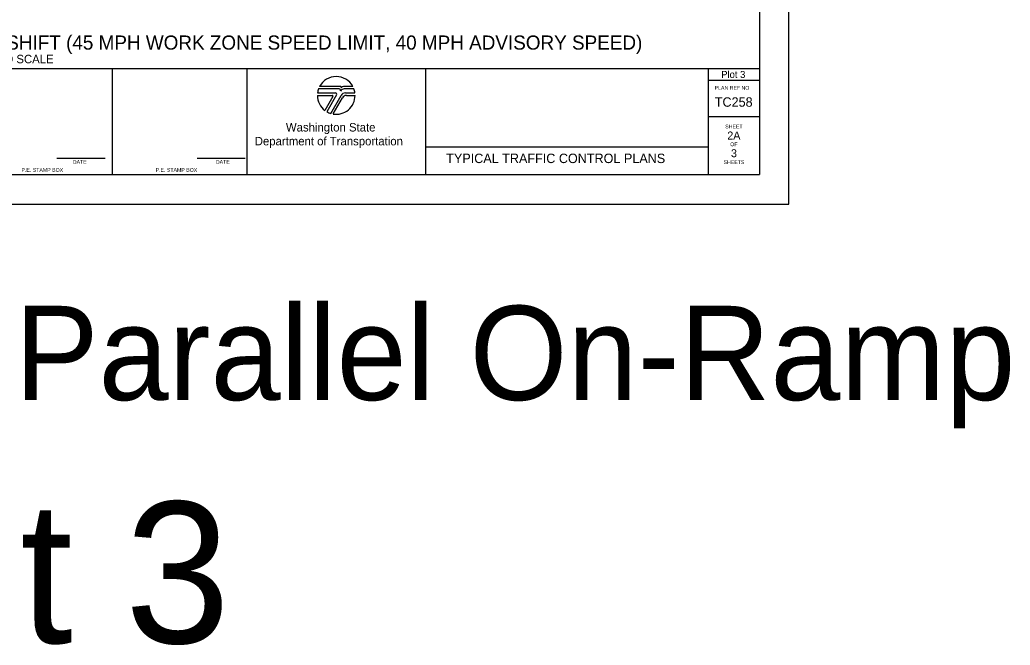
# Model space of a CAD drawing. Extents: x 99999 to 100116, y 99995 to 100013.
# Drawn here: x 100047.9 to 100058.41, y 99995.01 to 100001.64 of the extents above; entities that cross this region are included whole.
import ezdxf

# ---------------------------------------------------------------- set-up
doc = ezdxf.new("R2010")
doc.units = 0
for name, color, linetype in [('SH_DE_DetailHeading1Text', 7, 'Continuous'), ('SH_GI_PlotLimits', 7, 'Continuous'), ('SH_GI_SheetBorder', 7, 'Continuous'), ('SH_GI_SheetLocationText', 7, 'Continuous'), ('SH_GI_SheetTextInCells', 7, 'Continuous'), ('SH_GI_TitleBlockText', 7, 'Continuous'), ('SH_GI_WSDOTLogo', 7, 'Continuous')]:
    doc.layers.add(name, color=color, linetype=linetype)

msp = doc.modelspace()

# ---------------------------------------------------------------- linework, layer by layer
at = {"layer": 'SH_GI_PlotLimits'}
msp.add_lwpolyline([(100039.062, 99999.687), (100056.062, 99999.687), (100056.062, 100010.687), (100039.062, 100010.687)], close=True, dxfattribs=at)
at = {"layer": 'SH_GI_SheetBorder'}
for p, q in [((100055.75, 100010.375), (100055.75, 100000)), ((100040, 100001.126), (100055.75, 100001.126)), ((100048.883, 100000), (100048.883, 100001.126)), ((100050.309, 100001.126), (100050.309, 100000)), ((100052.205, 100001.126), (100052.205, 100000)), ((100055.208, 100001.126), (100055.208, 100000)), ((100055.208, 100001.001), (100055.75, 100001.001)), ((100055.208, 100000.618), (100055.75, 100000.618)), ((100052.205, 100000.295), (100055.208, 100000.295)), ((100048.29, 100000.173), (100048.802, 100000.173)), ((100049.78, 100000.173), (100050.291, 100000.173)), ((100040, 100000), (100055.75, 100000))]:
    msp.add_line(p, q, dxfattribs=at)
at = {"layer": 'SH_GI_WSDOTLogo'}
for p, q in [((100051.303, 100000.935), (100051.081, 100000.935)), ((100051.433, 100000.935), (100051.335, 100000.935)), ((100051.057, 100000.84), (100051.215, 100000.84)), ((100051.059, 100000.866), (100051.25, 100000.866)), ((100051.289, 100000.909), (100051.07, 100000.909)), ((100051.222, 100000.828), (100051.136, 100000.681)), ((100051.261, 100000.846), (100051.157, 100000.667)), ((100051.199, 100000.649), (100051.309, 100000.839)), ((100051.224, 100000.643), (100051.324, 100000.816)), ((100051.445, 100000.909), (100051.343, 100000.909)), ((100051.343, 100000.909), (100051.343, 100000.909)), ((100051.356, 100000.866), (100051.456, 100000.866)), ((100051.365, 100000.839), (100051.457, 100000.839))]:
    msp.add_line(p, q, dxfattribs=at)
for centre, radius, start, end in [((100051.257, 100000.84), 0.2, 28.4787, 151.532), ((100051.303, 100000.926), 0.00903, 329.8742, 90.0033), ((100051.335, 100000.907), 0.0287, 90.0072, 148.1676), ((100051.257, 100000.84), 0.2, 179.9986, 232.8433), ((100051.257, 100000.84), 0.2, 159.696, 172.5057), ((100051.215, 100000.832), 0.0082, 329.7436, 90), ((100051.257, 100000.84), 0.2, 260.5455, 359.8086), ((100051.25, 100000.853), 0.0131, 329.7683, 90), ((100051.289, 100000.895), 0.0148, 327.8418, 89.9985), ((100051.343, 100000.861), 0.0484, 89.9953, 147.8238), ((100051.356, 100000.812), 0.0542, 90, 149.9974), ((100051.365, 100000.792), 0.0476, 90, 150.0543), ((100051.257, 100000.84), 0.2, 7.4943, 20.2941), ((100051.257, 100000.84), 0.2, 239.7929, 253.0448)]:
    msp.add_arc(centre, radius, start, end, dxfattribs=at)

# ---------------------------------------------------------------- texts
at = {"layer": 'SH_DE_DetailHeading1Text'}
for s, height, p in [("FREEWAY (2 LANES): SINGLE RIGHT LANE CLOSURE, 9' MAX LEFT SHOULDER SHIFT (45 MPH WORK ZONE SPEED LIMIT, 40 MPH ADVISORY SPEED)", 0.15, (100040.091, 100001.326)), ('NOT TO SCALE', 0.09, (100047.373, 100001.181))]:
    msp.add_text(s, height=height, rotation=360, dxfattribs=at).set_placement(p)
at = {"layer": 'SH_GI_SheetBorder'}
msp.add_text('PLAN REF NO', height=0.04003, dxfattribs=at).set_placement((100055.275, 100000.901))
at = {"layer": 'SH_GI_SheetLocationText'}
for s, height, p in [('Plot 3', 0.075, (100055.345, 100001.025)), ('Right Ramps: Parallel On-Ramp', 1, (100039.37, 99997.607)), ('Plot 3', 1.5, (100045.001, 99995.027))]:
    msp.add_text(s, height=height, dxfattribs=at).set_placement(p)
at = {"layer": 'SH_GI_SheetTextInCells'}
for s, height, p in [('Washington State', 0.09007, (100050.723, 100000.457)), ('SHEET', 0.04, (100055.388, 100000.49)), ('Department of Transportation', 0.09007, (100050.392, 100000.31)), ('OF', 0.04, (100055.441, 100000.301)), ('DATE', 0.04, (100048.46, 100000.114)), ('DATE', 0.04, (100049.979, 100000.114)), ('SHEETS', 0.04, (100055.37, 100000.112)), ('P.E. STAMP BOX', 0.04003, (100047.915, 100000.029)), ('P.E. STAMP BOX', 0.04003, (100049.339, 100000.029))]:
    msp.add_text(s, height=height, dxfattribs=at).set_placement(p)
at = {"layer": 'SH_GI_TitleBlockText'}
for s, height, p in [('TC258', 0.1, (100055.277, 100000.72)), ('2A', 0.085, (100055.41, 100000.372)), ('TYPICAL TRAFFIC CONTROL PLANS', 0.1, (100052.425, 100000.122)), ('3', 0.085, (100055.449, 100000.184))]:
    msp.add_text(s, height=height, dxfattribs=at).set_placement(p)

doc.saveas('drawing.dxf')
